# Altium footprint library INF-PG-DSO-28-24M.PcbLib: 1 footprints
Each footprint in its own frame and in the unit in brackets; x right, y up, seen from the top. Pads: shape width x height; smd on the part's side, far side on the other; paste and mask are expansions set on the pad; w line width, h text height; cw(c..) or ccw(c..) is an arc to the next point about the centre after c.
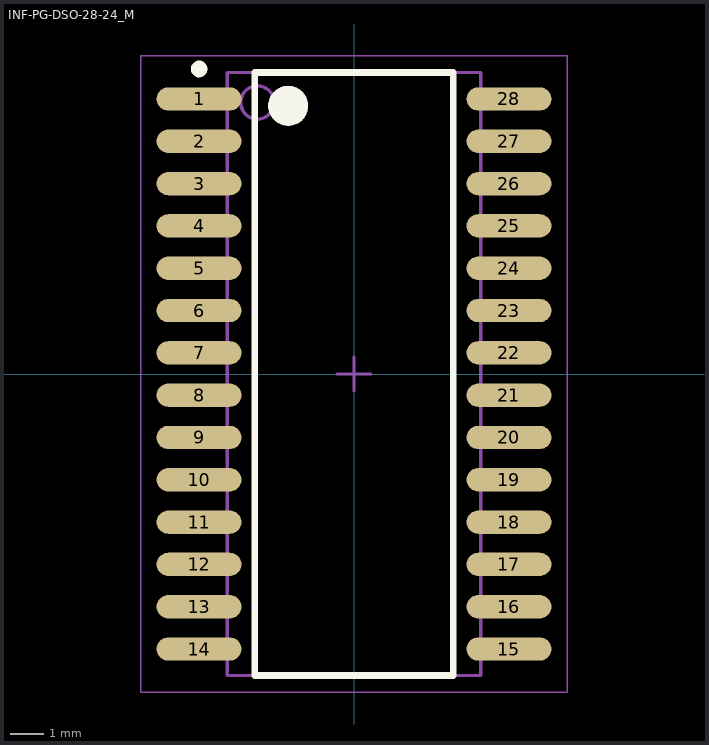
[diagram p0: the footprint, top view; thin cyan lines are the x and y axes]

## INF-PG-DSO-28-24_M [mm] "SOP, 28-Leads, Body 17.9x7.5mm, Pitch 1.27mm, IPC Low Density"
height 2.65
pads (28):
  oval 2.55x0.7 smd: 1(-4.65,8.255) 2(-4.65,6.985) 3(-4.65,5.715) 4(-4.65,4.445) 5(-4.65,3.175) 6(-4.65,1.905) 7(-4.65,0.635) 8(-4.65,-0.635) 9(-4.65,-1.905) 10(-4.65,-3.175) 11(-4.65,-4.445) 12(-4.65,-5.715) 13(-4.65,-6.985) 14(-4.65,-8.255) 15(4.65,-8.255) 16(4.65,-6.985) 17(4.65,-5.715) 18(4.65,-4.445) 19(4.65,-3.175) 20(4.65,-1.905) 21(4.65,-0.635) 22(4.65,0.635) 23(4.65,1.905) 24(4.65,3.175) 25(4.65,4.445) 26(4.65,5.715) 27(4.65,6.985) 28(4.65,8.255)
Top Overlay:
  circle w0.25: c-4.65,9.155 r0.125
  circle w0.6: c-1.975,8.05 r0.3
  lines w0.2: -2.975,-9.05 -2.975,9.05 2.975,9.05 2.975,-9.05 -2.975,-9.05
Mechanical 13:
  circle w0.1: c-2.9,8.15 r0.5
  lines w0.1: -3.8,-9.05 -3.8,9.05 3.8,9.05 3.8,-9.05 -3.8,-9.05
Mechanical 15:
  lines w0.05: -6.4,-9.55 -6.4,9.55 6.4,9.55 6.4,-9.55 -6.4,-9.55
  lines w0.1: -0.5,0 0.5,0 ; 0,-0.5 0,0.5
3D body: height 2.65, standoff 0.1, extent -3.8,-9.05 3.8,9.05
